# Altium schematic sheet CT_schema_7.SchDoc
size 364 x 245 mm
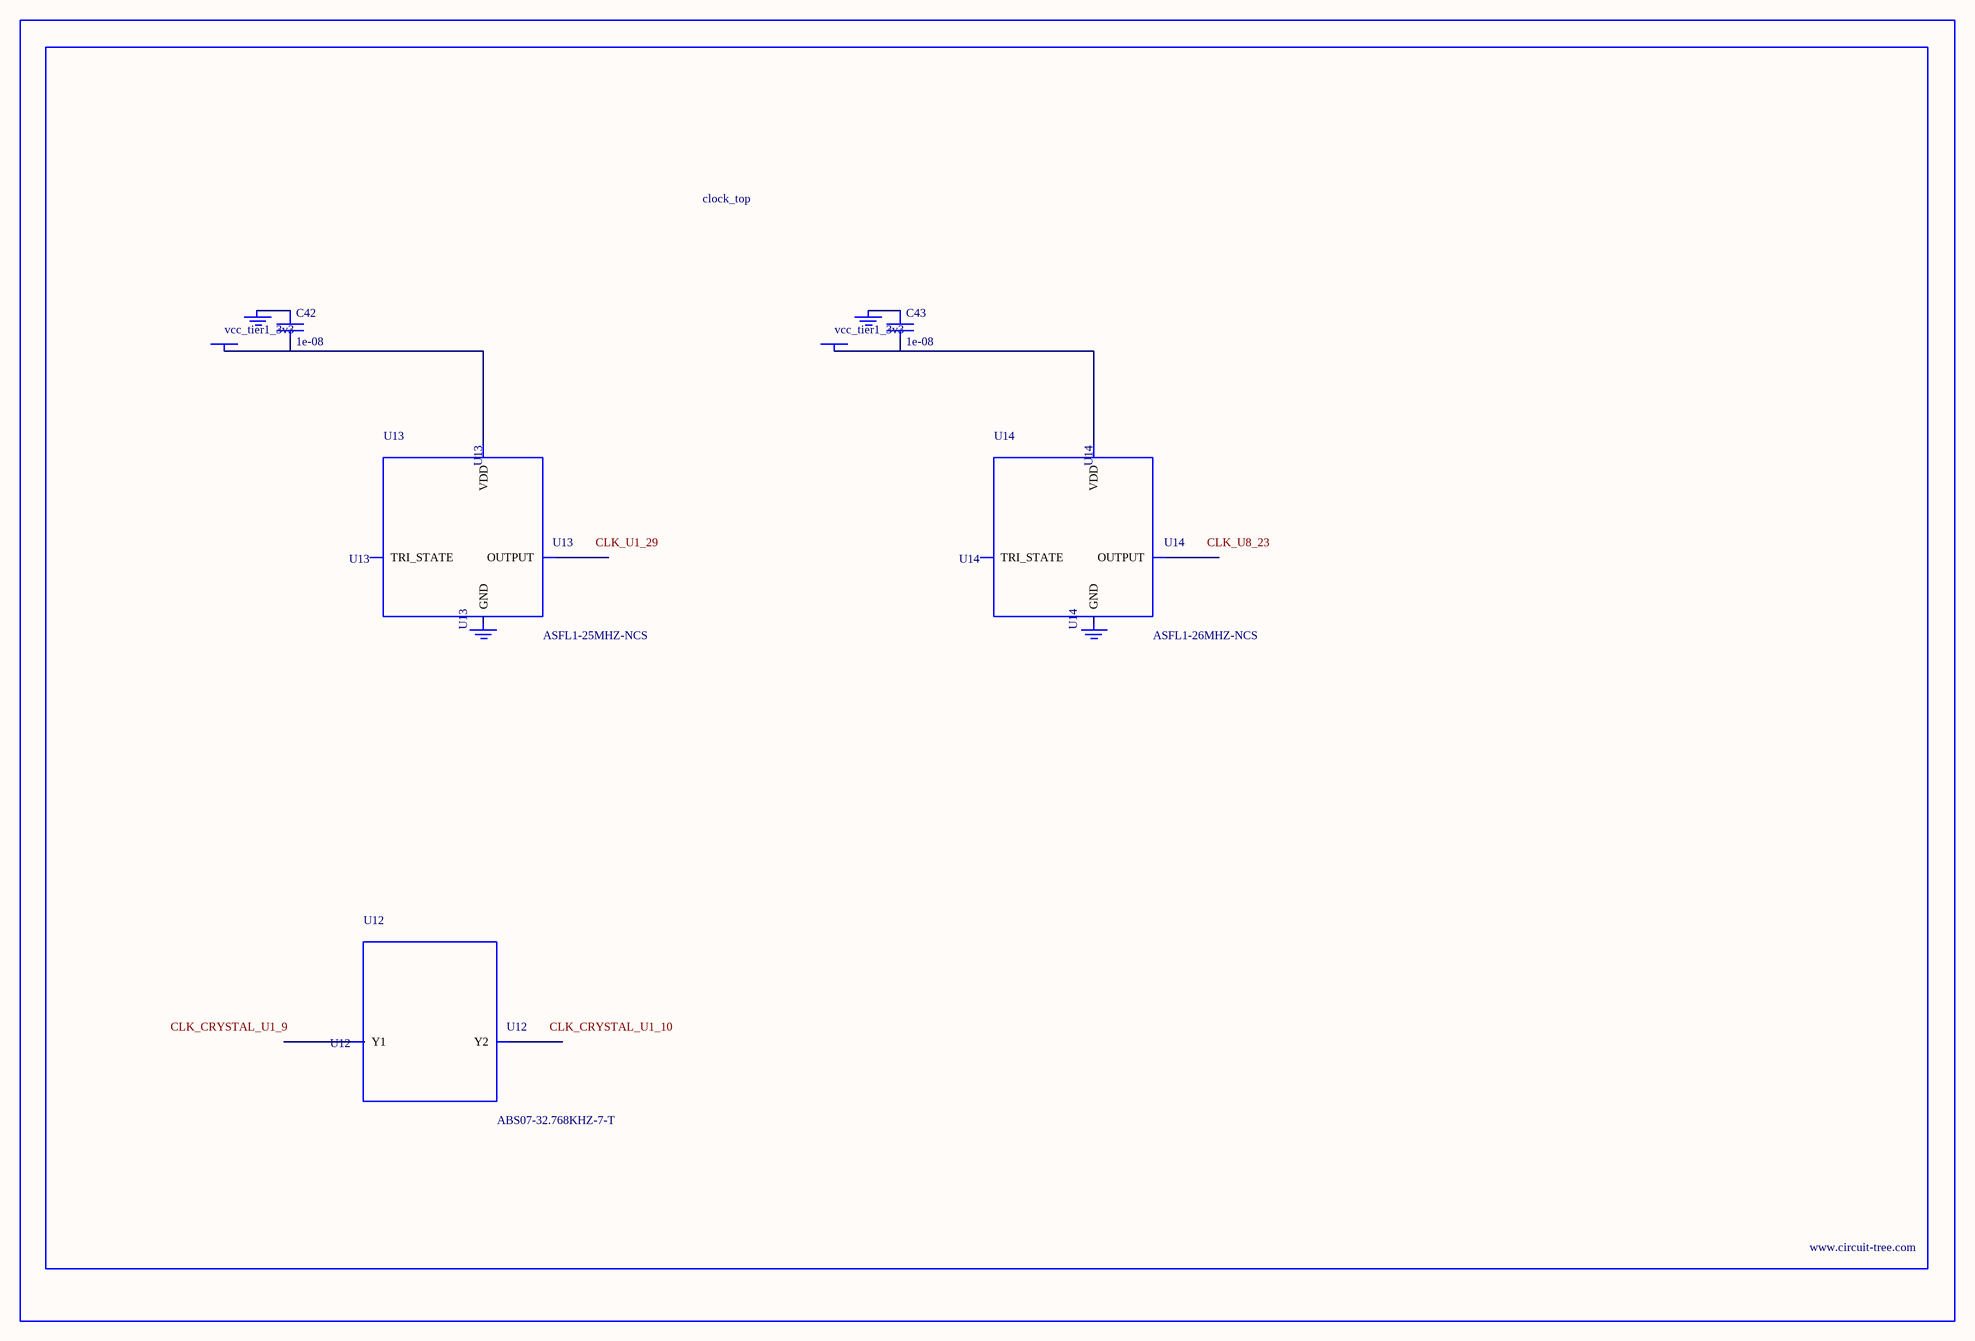
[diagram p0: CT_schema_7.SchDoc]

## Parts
BORDER6  (no value)
C42  1e-08  [C0402]
C43  1e-08  [C0402]
GND_INSTANCE_6_0  (no value)
GND_INSTANCE_6_1  (no value)
GND_INSTANCE_6_2  (no value)
GND_INSTANCE_6_3  (no value)
POWER_INSTANCE_6_0  vcc_tier1_3v3
POWER_INSTANCE_6_1  vcc_tier1_3v3
U12  ABS07-32.768KHZ-7-T  [ABS07-32.768KHZ-7-T]
U13  ASFL1-25MHZ-NCS  [ASFL1]
U14  ASFL1-26MHZ-NCS  [ASFL1]

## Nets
NetC42_1: C42.1 GND_INSTANCE_6_0.0(GND)
NetC42_2: C42.2 POWER_INSTANCE_6_0.0(PWR) U13.4(VDD)
NetC43_1: C43.1 GND_INSTANCE_6_2.0(GND)
NetC43_2: C43.2 POWER_INSTANCE_6_1.0(PWR) U14.4(VDD)

Not connected (* = marked no-connect by the designer): GND_INSTANCE_6_1 0(GND); GND_INSTANCE_6_3 0(GND); U12 1(Y1) 2(Y2); U13 1(TRI_STATE) 2(GND) 3(OUTPUT); U14 1(TRI_STATE) 2(GND) 3(OUTPUT)

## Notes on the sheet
- Labels drawn without touching a wire or pin: CLK_CRYSTAL_U1_9, CLK_CRYSTAL_U1_10, CLK_U1_29, CLK_U8_23

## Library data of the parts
BORDER6 = BORDER_PAGE6
C42 C43 = C0402C103K3RAC
GND_INSTANCE_6_0-GND_INSTANCE_6_3 = GND
POWER_INSTANCE_6_0 POWER_INSTANCE_6_1 = PWR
